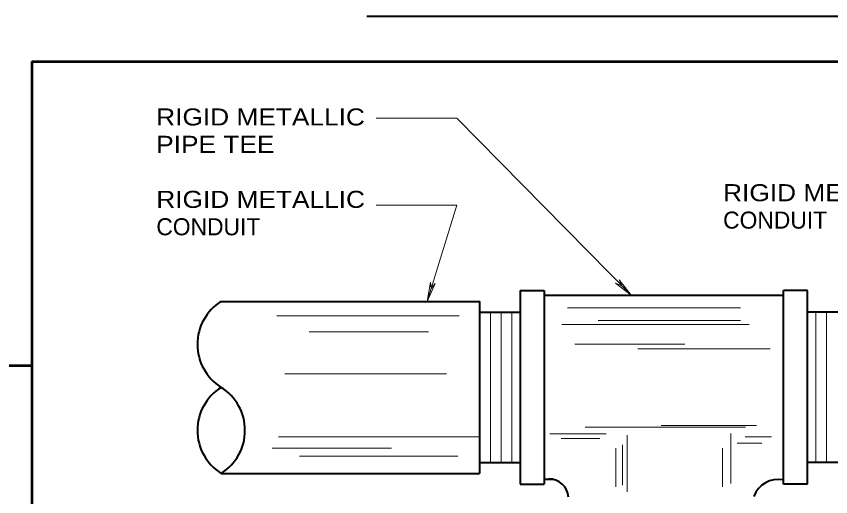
# Model space of a CAD drawing. Extents: x 312583 to 312854, y 144419 to 144597.
# Drawn here: x 312741.44 to 312777.68, y 144521.61 to 144543.02 of the extents above; entities that cross this region are included whole.
import ezdxf

# ---------------------------------------------------------------- set-up
doc = ezdxf.new("R2010")
doc.units = 0
doc.header["$LTSCALE"] = 0.3
doc.layers.add('1', color=7, linetype='Continuous', lineweight=40)
doc.layers.add('2', color=7, linetype='Continuous', lineweight=13)

msp = doc.modelspace()

# ---------------------------------------------------------------- linework, layer by layer
at = {"layer": '1', "lineweight": 53}
for p, q in [((312742.1369, 144540.9979), (312742.1369, 144423.0846)), ((312742.1369, 144540.9979), (312796.6103, 144540.9979)), ((312742.1369, 144527.439), (312675.4374, 144527.439))]:
    msp.add_line(p, q, dxfattribs=at)
at = {"layer": '1'}
for p, q in [((312764.9322, 144530.5866), (312775.6042, 144530.5866)), ((312764.9705, 144530.5866), (312765.3309, 144530.5866)), ((312764.9322, 144522.3909), (312765.3309, 144522.3909))]:
    msp.add_line(p, q, dxfattribs=at)
for centre, radius, start, end in [((312751.7589, 144528.4035), 2.2633, 122.12803, 237.87197), ((312751.7589, 144524.5701), 2.2633, 122.12803, 237.87197), ((312749.3517, 144524.5701), 2.2633, 302.12803, 57.87197), ((312765.1521, 144521.5364), 0.8648, 3.66127, 92.3778), ((312775.3364, 144521.2451), 1.1419, 78.99571, 160.4026)]:
    msp.add_arc(centre, radius, start, end, dxfattribs=at)
at = {"layer": '2', "lineweight": 40}
for p, q in [((312757.0299, 144543.0159), (312792.7483, 144543.0159)), ((312763.8589, 144530.8012), (312763.8589, 144522.1762)), ((312763.8589, 144530.8012), (312764.9322, 144530.8012)), ((312764.9322, 144530.8012), (312764.9322, 144522.1762)), ((312775.5735, 144522.1762), (312775.5735, 144530.8012)), ((312776.6469, 144530.8012), (312775.5735, 144530.8012)), ((312776.6469, 144522.1762), (312776.6469, 144530.8012)), ((312762.0572, 144529.8429), (312763.8589, 144529.8429)), ((312778.4485, 144529.8429), (312776.6469, 144529.8429)), ((312762.0572, 144523.1346), (312763.8589, 144523.1346)), ((312778.4485, 144523.1346), (312776.6469, 144523.1346)), ((312750.5572, 144522.6516), (312762.0572, 144522.6516)), ((312763.8589, 144522.1762), (312764.9322, 144522.1762)), ((312776.6469, 144522.1762), (312775.5735, 144522.1762))]:
    msp.add_line(p, q, dxfattribs=at)
at = {"layer": '2'}
for p, q in [((312761.0452, 144538.4832), (312757.4495, 144538.4832)), ((312761.0452, 144538.4832), (312768.7962, 144530.5866)), ((312761.0452, 144534.6039), (312757.4495, 144534.6039)), ((312761.0452, 144534.6039), (312759.7189, 144530.3182)), ((312759.7189, 144530.3182), (312759.8722, 144531.1769)), ((312759.7189, 144530.3182), (312760.0792, 144531.1156)), ((312759.8722, 144531.1769), (312759.8952, 144530.8856)), ((312760.0792, 144531.1156), (312759.8952, 144530.8856)), ((312768.1062, 144531.1309), (312768.3822, 144531.0082)), ((312768.7962, 144530.5866), (312768.1062, 144531.1309)), ((312768.2595, 144531.2766), (312768.3822, 144531.0082)), ((312768.7962, 144530.5866), (312768.2595, 144531.2766)), ((312762.5325, 144529.8429), (312762.5325, 144523.1346)), ((312763.0155, 144529.8429), (312763.0155, 144523.1346)), ((312763.4909, 144529.8429), (312763.4909, 144523.1346)), ((312765.9672, 144530.0346), (312773.6569, 144530.0346)), ((312777.0149, 144523.1346), (312777.0149, 144529.8429)), ((312777.4902, 144523.1346), (312777.4902, 144529.8429)), ((312753.0335, 144529.6742), (312761.1525, 144529.6742)), ((312765.7142, 144529.2832), (312774.0555, 144529.2832)), ((312767.3319, 144529.4596), (312773.6569, 144529.4596)), ((312754.4672, 144528.9536), (312759.7879, 144528.9536)), ((312766.2892, 144528.4169), (312771.1805, 144528.4169)), ((312769.0952, 144528.2022), (312774.9909, 144528.2022)), ((312753.3939, 144527.0829), (312760.5775, 144527.0829)), ((312770.1379, 144524.7829), (312774.3775, 144524.7829)), ((312765.1775, 144524.4226), (312767.6922, 144524.4226)), ((312766.7569, 144524.7139), (312773.8792, 144524.7139)), ((312773.2275, 144522.1992), (312773.2275, 144524.4302)), ((312753.1025, 144524.2846), (312762.0189, 144524.2846)), ((312765.6835, 144524.2079), (312767.4085, 144524.2079)), ((312768.6275, 144521.8389), (312768.6275, 144524.3536)), ((312773.8715, 144524.2846), (312775.0369, 144524.2846)), ((312752.8189, 144523.7786), (312758.1395, 144523.7786)), ((312768.1215, 144522.0536), (312768.1215, 144523.7786)), ((312768.4129, 144522.1302), (312768.4129, 144523.9319)), ((312772.8672, 144522.0536), (312772.8672, 144523.7786)), ((312773.5112, 144523.9932), (312774.6152, 144523.9932)), ((312754.0379, 144523.4182), (312761.0835, 144523.4182))]:
    msp.add_line(p, q, dxfattribs=at)
at = {"layer": '2', "lineweight": 40}
msp.add_lwpolyline([(312750.5572, 144530.3182), (312762.0572, 144530.3182), (312762.0572, 144522.6516)], dxfattribs=at)

# ---------------------------------------------------------------- texts
at = {"layer": '2', "width": 1.15}
for s, p in [('RIGID METALLIC', (312747.6643, 144538.1507)), ('PIPE TEE', (312747.6643, 144536.9307)), ('RIGID METALLIC', (312772.8896, 144534.7773)), ('RIGID METALLIC', (312747.6682, 144534.4803))]:
    msp.add_text(s, height=0.76, dxfattribs=at).set_placement(p)
at = {"layer": '2'}
for p in [(312772.8896, 144533.5573), (312747.6682, 144533.2603)]:
    msp.add_text('CONDUIT', height=0.76, dxfattribs=at).set_placement(p)

doc.saveas('drawing.dxf')
